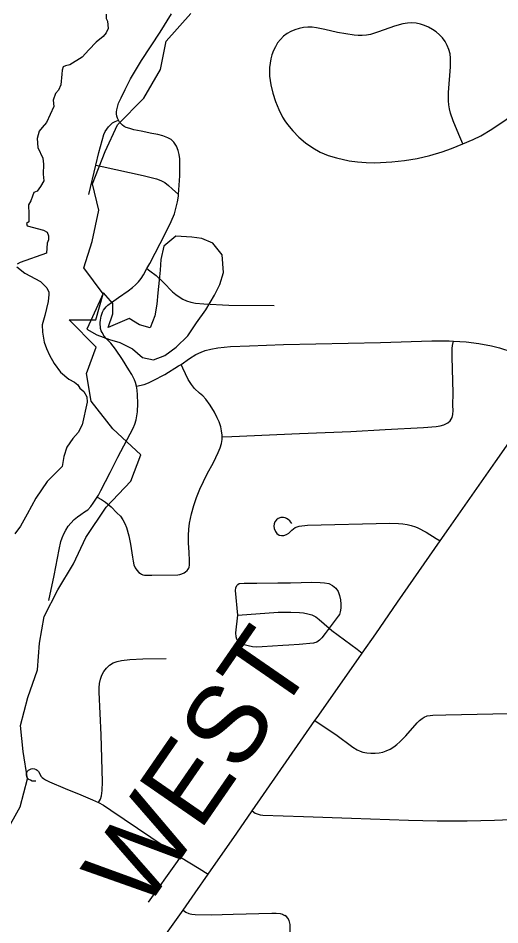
# Model space of a CAD drawing. Extents: x 0 to 34, y 0 to 22.
# Drawn here: x 5.8073 to 5.9825, y 19.5193 to 19.8487 of the extents above; entities that cross this region are included whole.
import ezdxf

# ---------------------------------------------------------------- set-up
doc = ezdxf.new("R2010")
doc.units = 0
for name, color, linetype in [('GM_X_Corporation', 7, 'Continuous'), ('GM_X_County_Road', 7, 'Continuous'), ('GM_X_County_Road_Text', 7, 'Continuous'), ('GM_X_Major_Lake', 7, 'Continuous'), ('GM_X_Minor_River', 7, 'Continuous'), ('GM_X_Township_Road', 7, 'Continuous')]:
    doc.layers.add(name, color=color, linetype=linetype)

msp = doc.modelspace()

# ---------------------------------------------------------------- linework, layer by layer
at = {"layer": 'GM_X_Corporation'}
for points in [[(5.83939, 19.85013), (5.83935, 19.84857), (5.83987, 19.84761), (5.84013, 19.84496), (5.83939, 19.84327), (5.83822, 19.84197), (5.8357, 19.83988), (5.833, 19.83719), (5.8306, 19.83447), (5.8261, 19.83175), (5.82462, 19.83132), (5.82366, 19.83095), (5.8234, 19.82976), (5.82327, 19.82837), (5.82288, 19.82446), (5.822, 19.82253), (5.82097, 19.82133), (5.8201, 19.8189), (5.82027, 19.81659), (5.81767, 19.81081), (5.8161, 19.80899), (5.81502, 19.80764), (5.81432, 19.8049), (5.81455, 19.80165), (5.81627, 19.79782), (5.81658, 19.79565), (5.81649, 19.79196), (5.81671, 19.78953), (5.81549, 19.78753), (5.81432, 19.78579), (5.81302, 19.78531), (5.81258, 19.78396), (5.81193, 19.78236), (5.81115, 19.78084), (5.81128, 19.77749), (5.81128, 19.77471), (5.81037, 19.77402), (5.81058, 19.77323), (5.81662, 19.77162), (5.81788, 19.77093), (5.81841, 19.76954), (5.81841, 19.76819), (5.81788, 19.76698), (5.81762, 19.76324), (5.80806, 19.75994), (5.80694, 19.75933)], [(5.83939, 19.85013), (5.83935, 19.84857), (5.83987, 19.84761), (5.84013, 19.84496), (5.83939, 19.84327), (5.83822, 19.84197), (5.8357, 19.83988), (5.833, 19.83719), (5.8306, 19.83447), (5.8261, 19.83175), (5.82462, 19.83132), (5.82366, 19.83095), (5.8234, 19.82976), (5.82327, 19.82837), (5.82288, 19.82446), (5.822, 19.82253), (5.82097, 19.82133), (5.8201, 19.8189), (5.82027, 19.81659), (5.81767, 19.81081), (5.8161, 19.80899), (5.81502, 19.80764), (5.81432, 19.8049), (5.81455, 19.80165), (5.81627, 19.79782), (5.81658, 19.79565), (5.81649, 19.79196), (5.81671, 19.78953), (5.81549, 19.78753), (5.81432, 19.78579), (5.81302, 19.78531), (5.81258, 19.78396), (5.81193, 19.78236), (5.81115, 19.78084), (5.81128, 19.77749), (5.81128, 19.77471), (5.81037, 19.77402), (5.81058, 19.77323), (5.81662, 19.77162), (5.81788, 19.77093), (5.81841, 19.76954), (5.81841, 19.76819), (5.81788, 19.76698), (5.81762, 19.76324), (5.80806, 19.75994), (5.80694, 19.75933)], [(5.80685, 19.75833), (5.8098, 19.75598), (5.81549, 19.75294), (5.81775, 19.75068), (5.81853, 19.74916), (5.81853, 19.74825), (5.81823, 19.74573), (5.8171, 19.74069), (5.81606, 19.73726), (5.81623, 19.73457), (5.8168, 19.73092), (5.81767, 19.72861), (5.81875, 19.72618), (5.8204, 19.72323), (5.82271, 19.7201), (5.82575, 19.71753), (5.82783, 19.7164), (5.82909, 19.71549), (5.82979, 19.71423), (5.83118, 19.71306), (5.83231, 19.71106), (5.83244, 19.70915), (5.83066, 19.70089), (5.82914, 19.69816), (5.82718, 19.69599), (5.82505, 19.69277), (5.82401, 19.68938), (5.82331, 19.68577), (5.82127, 19.68378), (5.81788, 19.68034), (5.81375, 19.67435), (5.81067, 19.66853), (5.80824, 19.66409), (5.80611, 19.6614)], [(5.80685, 19.75833), (5.8098, 19.75598), (5.81549, 19.75294), (5.81775, 19.75068), (5.81853, 19.74916), (5.81853, 19.74825), (5.81823, 19.74573), (5.8171, 19.74069), (5.81606, 19.73726), (5.81623, 19.73457), (5.8168, 19.73092), (5.81767, 19.72861), (5.81875, 19.72618), (5.8204, 19.72323), (5.82271, 19.7201), (5.82575, 19.71753), (5.82783, 19.7164), (5.82909, 19.71549), (5.82979, 19.71423), (5.83118, 19.71306), (5.83231, 19.71106), (5.83244, 19.70915), (5.83066, 19.70089), (5.82914, 19.69816), (5.82718, 19.69599), (5.82505, 19.69277), (5.82401, 19.68938), (5.82331, 19.68577), (5.82127, 19.68378), (5.81788, 19.68034), (5.81375, 19.67435), (5.81067, 19.66853), (5.80824, 19.66409), (5.80611, 19.6614)]]:
    msp.add_lwpolyline(points, dxfattribs=at)
at = {"layer": 'GM_X_County_Road'}
msp.add_line((5.89243, 19.56074), (5.91524, 19.59357), dxfattribs=at)
for points in [[(5.96072, 19.65878), (5.96387, 19.66331), (5.98086, 19.68747), (5.99333, 19.70531), (5.9989, 19.71332)], [(5.93245, 19.61805), (5.93732, 19.62499), (5.94523, 19.63652), (5.96072, 19.65878)], [(5.91524, 19.59357), (5.91599, 19.59466), (5.93109, 19.6161), (5.93245, 19.61805)], [(5.87643, 19.53766), (5.8868, 19.55262), (5.89243, 19.56074)], [(5.8673, 19.52463), (5.87174, 19.53091), (5.87643, 19.53766)], [(5.82574, 19.46506), (5.82902, 19.46973), (5.83877, 19.48378), (5.86188, 19.51695), (5.8673, 19.52463)]]:
    msp.add_lwpolyline(points, dxfattribs=at)
at = {"layer": 'GM_X_Major_Lake'}
msp.add_lwpolyline([(5.80278, 19.55262), (5.80809, 19.56212), (5.81074, 19.57238), (5.80922, 19.58226), (5.80827, 19.59176), (5.81093, 19.60183), (5.81434, 19.6119), (5.8151, 19.62159), (5.8168, 19.63128), (5.82173, 19.64097), (5.82742, 19.65047), (5.83198, 19.65997), (5.83937, 19.67099), (5.84829, 19.6805), (5.85189, 19.69), (5.84183, 19.6995), (5.83386, 19.70957), (5.83215, 19.71964), (5.83575, 19.72914), (5.82589, 19.73902), (5.83556, 19.73902), (5.83822, 19.74853), (5.83119, 19.75802), (5.83423, 19.76753), (5.83669, 19.77893), (5.83441, 19.78843), (5.83896, 19.80022), (5.84351, 19.80991), (5.853, 19.8196), (5.85907, 19.83006), (5.86115, 19.84032), (5.87007, 19.85039)], dxfattribs=at)
at = {"layer": 'GM_X_Minor_River'}
msp.add_line((5.83834, 19.74885), (5.83233, 19.7357), dxfattribs=at)
msp.add_lwpolyline([(5.83233, 19.7357), (5.83595, 19.73362), (5.84052, 19.73193), (5.84432, 19.73081), (5.84889, 19.72855), (5.85251, 19.72534), (5.8565, 19.72459), (5.86067, 19.72614), (5.86483, 19.7292), (5.86899, 19.73321), (5.87219, 19.73798), (5.87558, 19.74275), (5.87878, 19.74809), (5.88066, 19.7519), (5.88196, 19.75628), (5.88155, 19.76274), (5.87811, 19.76691), (5.87412, 19.7686), (5.87051, 19.76916), (5.86462, 19.76951), (5.86027, 19.76587), (5.85916, 19.76093), (5.85899, 19.75712), (5.85863, 19.75351), (5.85808, 19.74894), (5.85773, 19.74476), (5.85699, 19.74057), (5.8553, 19.73619), (5.8515, 19.73731), (5.84769, 19.73957), (5.84012, 19.73631), (5.8418, 19.74126), (5.84178, 19.74506), (5.83834, 19.74885)], dxfattribs=at)
at = {"layer": 'GM_X_Township_Road'}
msp.add_line((5.83301, 19.7846), (5.83557, 19.79523), dxfattribs=at)
for points in [[(5.83608, 19.67468), (5.83651, 19.67536), (5.83698, 19.67617), (5.83744, 19.67704), (5.84079, 19.68357), (5.84356, 19.68923), (5.8492, 19.69977), (5.84976, 19.70122), (5.85021, 19.7027), (5.85054, 19.7042), (5.85074, 19.70571), (5.85087, 19.70874), (5.8507, 19.71181), (5.8506, 19.71354), (5.85037, 19.71493), (5.84997, 19.71637), (5.84962, 19.71724), (5.84916, 19.71827), (5.8487, 19.7192), (5.8476, 19.72088), (5.84523, 19.72469), (5.8428, 19.72838), (5.84101, 19.73058), (5.83935, 19.73232), (5.83864, 19.73312), (5.83784, 19.73442), (5.83754, 19.73508), (5.83734, 19.73587), (5.83724, 19.73651), (5.83718, 19.7374), (5.8372, 19.7381), (5.83728, 19.73895), (5.83742, 19.73972), (5.83758, 19.74044), (5.83779, 19.74115), (5.83807, 19.74185), (5.83841, 19.74254), (5.83885, 19.74322), (5.8393, 19.74378), (5.83997, 19.74445), (5.84128, 19.74542), (5.84384, 19.74721), (5.84736, 19.74964), (5.8489, 19.75079), (5.85007, 19.75181), (5.85114, 19.75293), (5.8521, 19.75414), (5.85297, 19.75543), (5.85419, 19.75768), (5.8552, 19.75952), (5.86094, 19.77054), (5.86295, 19.77474), (5.86414, 19.77761), (5.86497, 19.78048), (5.86526, 19.78198), (5.86561, 19.784), (5.86565, 19.78463), (5.86615, 19.79134), (5.86617, 19.796), (5.86609, 19.79755), (5.86591, 19.79909), (5.86554, 19.8006), (5.86491, 19.80219), (5.86399, 19.80358), (5.86295, 19.80456), (5.86179, 19.8052), (5.86, 19.80589), (5.8581, 19.80641), (5.8559, 19.80681), (5.85203, 19.80756), (5.84943, 19.80814), (5.84799, 19.80854), (5.84658, 19.80899), (5.8459, 19.80932), (5.84524, 19.80976), (5.84463, 19.81035), (5.84416, 19.8109), (5.84378, 19.81157), (5.84348, 19.8123), (5.84325, 19.81306), (5.84314, 19.81386), (5.84313, 19.81457), (5.84321, 19.81534), (5.84342, 19.81635), (5.84387, 19.81775), (5.84475, 19.81975), (5.84625, 19.82275), (5.84818, 19.82666), (5.85216, 19.83326), (5.85899, 19.84362), (5.86309, 19.85018)], [(5.96901, 19.80299), (5.96759, 19.80644), (5.96552, 19.81131), (5.96454, 19.81419), (5.96418, 19.81567), (5.96393, 19.81716), (5.96378, 19.81867), (5.96373, 19.82018), (5.96379, 19.8217), (5.96455, 19.83098), (5.96455, 19.83414), (5.96433, 19.83572), (5.96392, 19.83727), (5.96332, 19.83876), (5.96255, 19.84017), (5.9616, 19.84147), (5.9605, 19.84263), (5.95928, 19.84367), (5.95796, 19.84457), (5.95656, 19.84533), (5.9551, 19.84596), (5.95358, 19.84646), (5.95201, 19.84681), (5.95041, 19.84694), (5.94882, 19.84684), (5.94724, 19.84658), (5.94421, 19.84571), (5.93837, 19.84363), (5.93545, 19.84278), (5.93396, 19.84251), (5.93246, 19.84235), (5.93096, 19.84234), (5.92945, 19.84245), (5.92338, 19.84345), (5.91889, 19.84452), (5.91582, 19.8452), (5.91423, 19.84538), (5.91263, 19.84539), (5.91105, 19.84522), (5.90949, 19.8449), (5.90796, 19.84445), (5.90648, 19.84383), (5.90508, 19.84304), (5.9038, 19.84207), (5.90266, 19.84094), (5.90168, 19.83966), (5.90085, 19.83829), (5.90017, 19.83685), (5.89961, 19.83536), (5.89919, 19.83383), (5.8989, 19.83227), (5.89874, 19.83069), (5.89869, 19.82911), (5.89875, 19.82753), (5.89891, 19.82596), (5.89916, 19.82441), (5.8999, 19.82136), (5.90088, 19.81838), (5.90207, 19.81549), (5.90344, 19.81266), (5.90429, 19.81133), (5.90522, 19.81006), (5.90725, 19.80767), (5.90944, 19.80543), (5.91185, 19.8034), (5.91441, 19.80159), (5.91714, 19.80003), (5.92004, 19.7988), (5.92304, 19.79789), (5.92762, 19.79687), (5.93071, 19.79643), (5.93383, 19.7962), (5.93696, 19.79616), (5.94317, 19.79648), (5.94782, 19.79694), (5.95243, 19.79769), (5.95698, 19.79876), (5.96147, 19.80006), (5.9649, 19.80133), (5.96901, 19.80299)], [(5.96901, 19.80299), (5.9727, 19.80454), (5.97551, 19.80594), (5.97954, 19.80835), (5.9847, 19.81188), (5.98842, 19.81473), (5.99438, 19.81976), (6.0094, 19.83332), (6.01088, 19.83461)], [(5.83557, 19.79523), (5.83669, 19.79987), (5.83786, 19.80422), (5.83856, 19.80638), (5.83902, 19.80745), (5.83964, 19.80837), (5.8402, 19.80916), (5.84086, 19.80981), (5.84171, 19.8106), (5.84262, 19.81112), (5.84378, 19.81157)], [(5.83557, 19.79523), (5.83792, 19.79473), (5.85285, 19.79146), (5.85762, 19.79031), (5.85928, 19.7897), (5.86062, 19.78894), (5.86199, 19.78787), (5.86337, 19.78661), (5.86565, 19.78463)], [(5.85419, 19.75768), (5.85527, 19.75686), (5.85747, 19.75518), (5.86024, 19.75258), (5.86348, 19.74929), (5.86463, 19.74825), (5.86584, 19.74745), (5.86723, 19.74663), (5.8686, 19.74594), (5.87015, 19.74547), (5.87187, 19.74516), (5.87487, 19.7449), (5.88399, 19.74444), (5.90047, 19.74423)], [(5.86657, 19.7229), (5.86968, 19.72497), (5.87199, 19.72644), (5.87387, 19.72735), (5.87534, 19.72791), (5.87737, 19.7284), (5.87995, 19.72889), (5.88449, 19.72938), (5.89148, 19.72966), (5.9038, 19.73016), (5.93909, 19.7309), (5.95778, 19.73146), (5.96399, 19.73143), (5.96561, 19.73133)], [(5.88149, 19.69654), (5.88498, 19.69669), (5.90964, 19.69782), (5.92829, 19.69857), (5.94071, 19.69924), (5.95467, 19.69998), (5.95932, 19.70035), (5.96079, 19.70057), (5.96206, 19.70089), (5.96353, 19.70172), (5.96436, 19.70242), (5.96506, 19.70357), (5.96532, 19.70472), (5.96544, 19.70619), (5.96541, 19.7079), (5.96544, 19.71258), (5.96516, 19.72555), (5.96513, 19.72728), (5.96513, 19.72863), (5.96524, 19.72971), (5.96561, 19.73133)], [(5.96561, 19.73133), (5.97018, 19.73103), (5.97481, 19.73047), (5.97938, 19.72968), (5.98237, 19.72891), (5.98679, 19.72748), (5.98966, 19.72631), (5.99385, 19.72431), (5.99923, 19.72129), (6.00285, 19.71897)], [(5.85037, 19.71493), (5.85321, 19.7156), (5.85476, 19.7162), (5.85649, 19.71701), (5.86071, 19.71926), (5.8657, 19.72232), (5.86657, 19.7229)], [(5.88149, 19.69654), (5.8815, 19.6972), (5.88129, 19.69873), (5.881, 19.70024), (5.88038, 19.70199), (5.87968, 19.70352), (5.87877, 19.70555), (5.87716, 19.70813), (5.87555, 19.71023), (5.87444, 19.71142), (5.87325, 19.71247), (5.8715, 19.71414), (5.87038, 19.71554), (5.86919, 19.71743), (5.86723, 19.72148), (5.86657, 19.7229)], [(5.83608, 19.67468), (5.83761, 19.67386), (5.83906, 19.67288), (5.84114, 19.67109), (5.84327, 19.66901), (5.84454, 19.6677), (5.84538, 19.66641), (5.84611, 19.66504), (5.84673, 19.66362), (5.8476, 19.66064), (5.84817, 19.65754), (5.84887, 19.6529), (5.84912, 19.65138), (5.84944, 19.65009), (5.84986, 19.64903), (5.85048, 19.64811), (5.85124, 19.64734), (5.85181, 19.6469), (5.85221, 19.64664), (5.8527, 19.64647), (5.85329, 19.64636), (5.85397, 19.64636), (5.856, 19.64631), (5.86535, 19.64645), (5.86614, 19.64657), (5.86682, 19.64676), (5.86766, 19.64713), (5.8682, 19.64753), (5.86878, 19.64799), (5.8692, 19.64851), (5.86937, 19.64886), (5.86949, 19.64926), (5.86959, 19.65), (5.86966, 19.65157), (5.86948, 19.65466), (5.86927, 19.65796), (5.86927, 19.66076), (5.86934, 19.66306), (5.86969, 19.66523), (5.87039, 19.66858), (5.87116, 19.67159), (5.8722, 19.67452), (5.87339, 19.6776), (5.87612, 19.68312), (5.87835, 19.68724), (5.8801, 19.69088), (5.88082, 19.69263), (5.88123, 19.69413), (5.88148, 19.69566), (5.88149, 19.69654)], [(5.81853, 19.6371), (5.82045, 19.64622), (5.82225, 19.65567), (5.82289, 19.6585), (5.82335, 19.65994), (5.82398, 19.66133), (5.82468, 19.66266), (5.82554, 19.6641), (5.82647, 19.66526), (5.82768, 19.66653), (5.82895, 19.66756), (5.8301, 19.66838), (5.83143, 19.6693), (5.83265, 19.67011), (5.8338, 19.67126), (5.83467, 19.67248), (5.83608, 19.67468)], [(5.90681, 19.66505), (5.90651, 19.66557), (5.90607, 19.66609), (5.90555, 19.66658), (5.90495, 19.66693), (5.9044, 19.66713), (5.90378, 19.66724), (5.90282, 19.66724), (5.90192, 19.66688), (5.90123, 19.66642), (5.90069, 19.6657), (5.90036, 19.66502), (5.90028, 19.66412), (5.90041, 19.6633), (5.90085, 19.66223), (5.90143, 19.66146), (5.90222, 19.66089), (5.90307, 19.66073), (5.90397, 19.6607), (5.90493, 19.66105), (5.9058, 19.66157), (5.90635, 19.66215), (5.90681, 19.6627), (5.90805, 19.66363), (5.90948, 19.66415), (5.91258, 19.66445), (5.9425, 19.66521), (5.94564, 19.66513), (5.9472, 19.66498), (5.94875, 19.66473), (5.95027, 19.66435), (5.95177, 19.66386), (5.95265, 19.6635), (5.95562, 19.66193), (5.95925, 19.65968), (5.96072, 19.65878)], [(5.88715, 19.63182), (5.88635, 19.64076), (5.88646, 19.64177), (5.88687, 19.64257), (5.8872, 19.64298), (5.88764, 19.64326), (5.88951, 19.64342), (5.89413, 19.64348), (5.90178, 19.64356), (5.90639, 19.64353), (5.91409, 19.64376), (5.91719, 19.64371), (5.91874, 19.64356), (5.92025, 19.64324), (5.92165, 19.6426), (5.92279, 19.64161), (5.92363, 19.64034), (5.92416, 19.63889), (5.9245, 19.63737), (5.92468, 19.63583), (5.92466, 19.63428), (5.92442, 19.63298), (5.92412, 19.63208), (5.92371, 19.63138), (5.92038, 19.62704)], [(5.92038, 19.62704), (5.91892, 19.62513), (5.91771, 19.62362), (5.91689, 19.62272), (5.91594, 19.62198), (5.91466, 19.62162), (5.90947, 19.62118), (5.90569, 19.62087), (5.90359, 19.62076), (5.89611, 19.62032), (5.894, 19.62016), (5.89249, 19.62033), (5.891, 19.62061), (5.88949, 19.62101), (5.88812, 19.62164), (5.88753, 19.62201), (5.8871, 19.62261), (5.88682, 19.62311), (5.88656, 19.62393), (5.88646, 19.62534), (5.88715, 19.63182)], [(5.88715, 19.63182), (5.90181, 19.63288), (5.90647, 19.63292), (5.90958, 19.63275), (5.91113, 19.63259), (5.91267, 19.63233), (5.91414, 19.63187), (5.9155, 19.63114), (5.91673, 19.63021), (5.92038, 19.62704)], [(5.92038, 19.62704), (5.92138, 19.62618), (5.9306, 19.61941), (5.93245, 19.61805)], [(5.8366, 19.56374), (5.83726, 19.56494), (5.8377, 19.5662), (5.83793, 19.56813), (5.83801, 19.57123), (5.83748, 19.58833), (5.83718, 19.59609), (5.8368, 19.60387), (5.83683, 19.60542), (5.83697, 19.60697), (5.83728, 19.60849), (5.83779, 19.60996), (5.83851, 19.61133), (5.83946, 19.61257), (5.84061, 19.61362), (5.84192, 19.61443), (5.84336, 19.61501), (5.84487, 19.61538), (5.84797, 19.61568), (5.85263, 19.61594), (5.86113, 19.61608)], [(5.91524, 19.59357), (5.91858, 19.59125), (5.92279, 19.58843), (5.92479, 19.58703), (5.92713, 19.58531), (5.92902, 19.5839), (5.93056, 19.58293), (5.93171, 19.58236), (5.9326, 19.58209), (5.93404, 19.58181), (5.9356, 19.58167), (5.93713, 19.58161), (5.93856, 19.58174), (5.93986, 19.58206), (5.94116, 19.58251), (5.94258, 19.58316), (5.94386, 19.58393), (5.94504, 19.58481), (5.94615, 19.58579), (5.94827, 19.58797), (5.95243, 19.59263), (5.95329, 19.59355), (5.95417, 19.59425), (5.95495, 19.59471), (5.95607, 19.5952), (5.9571, 19.59541), (5.9581, 19.59549), (5.96281, 19.59563), (5.97991, 19.59591), (6.00166, 19.59627)], [(5.8138, 19.57152), (5.81314, 19.57148), (5.81249, 19.57152), (5.8118, 19.57181), (5.81128, 19.57212), (5.8109, 19.57244), (5.81062, 19.57278), (5.81048, 19.57321), (5.81042, 19.57363), (5.81042, 19.57433), (5.81064, 19.57496), (5.81108, 19.57544), (5.8116, 19.57579), (5.81213, 19.57599), (5.81274, 19.5761), (5.81331, 19.57602), (5.81386, 19.57579), (5.81432, 19.57549), (5.81473, 19.57502), (5.81522, 19.57418), (5.81565, 19.57337), (5.81607, 19.57286), (5.81657, 19.57247), (5.81732, 19.57198), (5.81877, 19.57128), (5.82439, 19.56879), (5.83014, 19.56649), (5.83436, 19.56468), (5.8366, 19.56374)], [(5.8366, 19.56374), (5.83841, 19.56275), (5.84105, 19.56102), (5.86526, 19.5446), (5.86636, 19.54392)], [(5.89243, 19.56074), (5.89356, 19.55992), (5.89459, 19.55947), (5.89537, 19.55926), (5.89628, 19.55916), (5.91103, 19.55865), (5.92854, 19.5581), (5.94919, 19.55738), (5.95964, 19.55706), (5.97055, 19.55709), (5.98055, 19.55738), (5.99796, 19.55805), (6.00333, 19.55823)], [(5.85475, 19.52751), (5.86522, 19.54231), (5.86636, 19.54392)], [(5.86636, 19.54392), (5.87312, 19.53972), (5.87643, 19.53766)], [(5.8673, 19.52463), (5.86834, 19.52396), (5.86944, 19.52344), (5.86989, 19.5233), (5.87047, 19.52313), (5.87167, 19.52303), (5.87751, 19.52298), (5.88546, 19.5232), (5.89953, 19.52359), (5.90109, 19.52359), (5.90264, 19.52344), (5.9034, 19.52322), (5.90386, 19.523), (5.90434, 19.52274)], [(5.90819, 19.47008), (5.90712, 19.48391), (5.90655, 19.49622), (5.90637, 19.50699), (5.90625, 19.5116), (5.90625, 19.51765), (5.90623, 19.51857), (5.90617, 19.51942), (5.90583, 19.52085), (5.90535, 19.52173), (5.90485, 19.52234), (5.90434, 19.52274)]]:
    msp.add_lwpolyline(points, dxfattribs=at)

# ---------------------------------------------------------------- texts
at = {"layer": 'GM_X_County_Road_Text'}
msp.add_text('WEST', height=0.028409, rotation=55.401, dxfattribs=at).set_placement((5.85291, 19.5234))

doc.saveas('drawing.dxf')
